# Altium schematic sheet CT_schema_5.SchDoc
size 278 x 170 mm
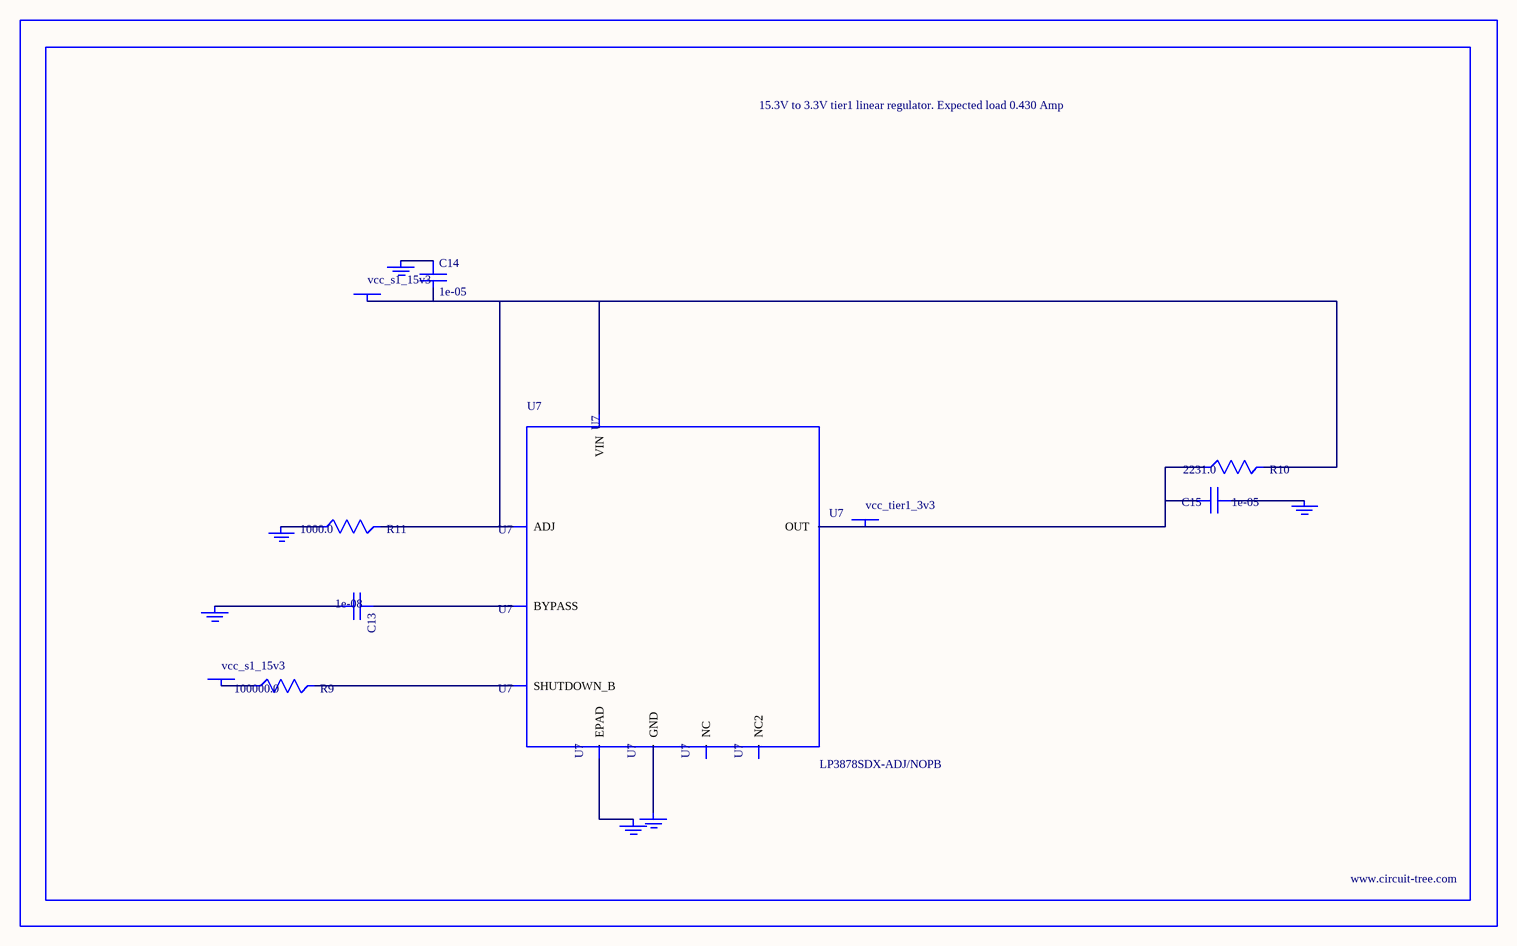
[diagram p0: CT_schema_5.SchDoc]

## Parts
BORDER4  (no value)
C13  1e-08  [C0402]
C14  1e-05  [C1210]
C15  1e-05  [C1210]
GND_INSTANCE_4_0  (no value)
GND_INSTANCE_4_1  (no value)
GND_INSTANCE_4_2  (no value)
GND_INSTANCE_4_3  (no value)
GND_INSTANCE_4_4  (no value)
GND_INSTANCE_4_5  (no value)
POWER_INSTANCE_4_0  vcc_s1_15v3
POWER_INSTANCE_4_1  vcc_s1_15v3
POWER_INSTANCE_4_2  vcc_tier1_3v3
R9  100000.0  [R0603]
R10  2231.0  [R0603]
R11  1000.0  [R0603]
U7  LP3878SDX-ADJ/NOPB  [WSON-8]

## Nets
NetC13_1: C13.1 U7.1(BYPASS)
NetC13_2: C13.2 GND_INSTANCE_4_0.0(GND)
NetC14_1: C14.1 GND_INSTANCE_4_1.0(GND)
NetC14_2: C14.2 POWER_INSTANCE_4_0.0(PWR) R10.2 R11.2 U7.4(VIN) U7.6(ADJ)
NetC15_1: C15.1 GND_INSTANCE_4_2.0(GND)
NetC15_2: C15.2 POWER_INSTANCE_4_2.0(PWR) R10.1 U7.5(OUT)
NetGND_INSTANCE_4_3_0: GND_INSTANCE_4_3.0(GND) R11.1
NetGND_INSTANCE_4_4_0: GND_INSTANCE_4_4.0(GND) U7.PAD(EPAD)
NetGND_INSTANCE_4_5_0: GND_INSTANCE_4_5.0(GND) U7.3(GND)
NetPOWER_INSTANCE_4_1_0: POWER_INSTANCE_4_1.0(PWR) R9.1
NetR9_2: R9.2 U7.8(SHUTDOWN_B)

Not connected (* = marked no-connect by the designer): U7 2(NC) 7(NC2)

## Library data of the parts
BORDER4 = BORDER_PAGE4
C13 = C0402C103K3RAC
C14 = C1210C106K5PACTU
C15 = GRM32DR61E106MA12L
GND_INSTANCE_4_0-GND_INSTANCE_4_5 = GND
POWER_INSTANCE_4_0-POWER_INSTANCE_4_2 = PWR
R9 = RC0603JR-07100KL
R10 = R10
R11 = RC0603JR-071KL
